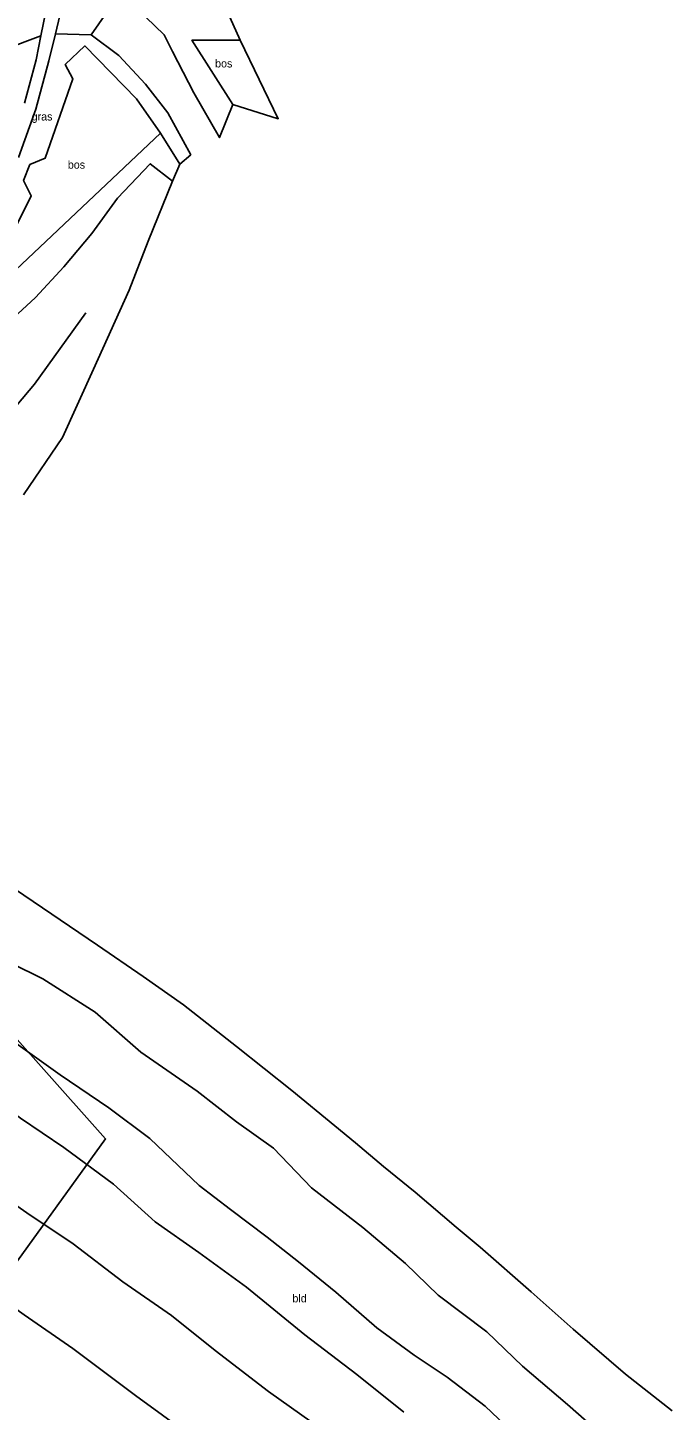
# Model space of a CAD drawing. Extents: x 154825 to 158680, y 370717 to 378075.
# Drawn here: x 157974.4 to 158055, y 372312.7 to 372485.5 of the extents above; entities that cross this region are included whole.
import ezdxf

# ---------------------------------------------------------------- set-up
doc = ezdxf.new("R2010")
doc.units = 0
for name, color, linetype in [('bos(vs)', 7, 'Continuous'), ('bouwland_akkerland(vs)', 7, 'Continuous'), ('cultuurscheiding', 7, 'Continuous'), ('grazige vegetatie(vs)', 7, 'Continuous'), ('hoogteverschillijn', 7, 'Continuous'), ('maaiveldlijn algemeen - gesloten verharding', 7, 'Continuous'), ('maaiveldlijn algemeen - onverhard', 7, 'Continuous'), ('maaiveldlijn algemeen - open verharding', 7, 'Continuous'), ('raster - hek', 7, 'Continuous'), ('vlak_akkerland', 7, 'Continuous'), ('vlak_Bos', 7, 'Continuous'), ('vlak_Grazige_vegetatie', 7, 'Continuous')]:
    doc.layers.add(name, color=color, linetype=linetype)

msp = doc.modelspace()

# ---------------------------------------------------------------- linework, layer by layer
at = {"layer": 'bos(vs)'}
for points in [[(158000.96, 372483.91), (157994.94, 372483.92), (158000.04, 372475.88)], [(157991.01, 372472.3), (157988.03, 372476.61), (157981.58, 372483.22), (157979.12, 372480.89), (157980.07, 372479.08), (157976.61, 372469.17), (157974.7, 372468.37), (157973.91, 372466.38), (157974.87, 372464.48), (157972.22, 372459.1), (157970.9, 372459.77), (157969.76, 372457.97), (157970.99, 372456.73), (157964.89, 372448.46), (157965.36, 372448.1)]]:
    msp.add_lwpolyline(points, dxfattribs=at)
at = {"layer": 'cultuurscheiding'}
msp.add_lwpolyline([(157970.2, 372327.32), (157984.17, 372346.6), (157927.5, 372410.28)], dxfattribs=at)
at = {"layer": 'hoogteverschillijn'}
for points in [[(157973.9, 372427.12), (157978.77, 372434.26), (157982.66, 372442.8), (157987.12, 372452.67), (157989.46, 372458.82), (157992.54, 372466.3), (157989.74, 372468.49), (157985.63, 372464.17), (157982.43, 372459.76), (157978.95, 372455.59), (157975.42, 372451.75), (157970.46, 372447.24)], [(157967.28, 372431.48), (157975.28, 372440.95), (157981.69, 372449.85)], [(157913.99, 372390.27), (157919.62, 372384.71), (157926.74, 372379.79), (157934.4, 372374.41), (157942.49, 372368.78), (157951.15, 372364.12), (157958.01, 372359.86), (157966.08, 372354.73), (157973.53, 372349.19), (157978.93, 372345.55), (157985.13, 372340.96), (157990.34, 372336.26), (157995.79, 372332.43), (158001.76, 372328.09), (158009.06, 372322.14), (158015.55, 372317.18), (158021.41, 372312.44)], [(158013.82, 372308.42), (158004.52, 372315.05), (157997.86, 372320.15), (157992.4, 372324.54), (157986.31, 372328.75), (157980.11, 372333.51), (157974.33, 372337.38), (157969.02, 372341.05), (157961.13, 372347.04), (157955.84, 372350.82), (157950.04, 372354.73), (157940.77, 372360.79), (157932.28, 372365.94), (157921.65, 372372.1), (157913.6, 372377.3), (157906.61, 372383.15), (157900.17, 372375.99), (157906.61, 372370.42), (157913.21, 372364.64)], [(158054.96, 372312.63), (158049.09, 372317.19), (158042.59, 372322.81), (158037.31, 372327.51), (158030.96, 372333.07), (158027.95, 372335.58), (158022.82, 372339.95), (158018.88, 372343.15), (158015.38, 372346.13), (158012.79, 372348.23), (158007.44, 372352.64), (158000.52, 372358.14), (157993.89, 372363.35), (157988.84, 372366.9), (157983.15, 372370.82), (157972.8, 372377.86)], [(157968.46, 372370.47), (157976.31, 372366.61), (157982.88, 372362.46), (157988.57, 372357.43), (157995.61, 372352.59), (158000.53, 372348.76), (158005.15, 372345.47), (158009.87, 372340.5), (158016.31, 372335.53), (158021.64, 372331.05), (158025.72, 372327.09), (158031.78, 372322.51), (158036.26, 372318.21), (158041.85, 372313.43), (158048.43, 372307.64)], [(157910.59, 372358.04), (157917.15, 372363.05), (157934.31, 372352.12), (157951.69, 372340.45), (157966.41, 372330.02), (157974, 372324.62), (157980.08, 372320.43), (157987.91, 372314.55), (157994.65, 372309.63)], [(158035.74, 372309.24), (158031.59, 372313.21), (158026.82, 372316.83), (158022.73, 372319.59), (158018.05, 372322.98), (158012.91, 372327.44), (158008.24, 372331.23), (158004.35, 372334.31), (157999.75, 372337.8), (157995.84, 372340.79), (157989.68, 372346.66), (157984.57, 372350.49), (157978.47, 372354.62), (157972.65, 372358.78)]]:
    msp.add_lwpolyline(points, dxfattribs=at)
at = {"layer": 'maaiveldlijn algemeen - gesloten verharding'}
for points in [[(157977.42, 372491.75), (157976.7, 372487.51), (157976.08, 372484.46)], [(157979.19, 372492.02), (157978.45, 372487.03), (157977.91, 372484.74)], [(157973.29, 372469.28), (157975.44, 372475.29), (157977.09, 372481.36), (157977.91, 372484.74)], [(157974.02, 372476.05), (157975.48, 372481.48), (157976.08, 372484.46)]]:
    msp.add_lwpolyline(points, dxfattribs=at)
at = {"layer": 'maaiveldlijn algemeen - onverhard'}
for points in [[(157998.41, 372471.76), (157995.2, 372477.35), (157992.51, 372482.51), (157991.46, 372484.61), (157988.08, 372487.9), (157985.23, 372488.72)], [(157982.36, 372484.59), (157985.81, 372482), (157989.13, 372478.43), (157991.93, 372474.83), (157994.79, 372469.6)]]:
    msp.add_lwpolyline(points, dxfattribs=at)
at = {"layer": 'maaiveldlijn algemeen - open verharding'}
for points in [[(157982.36, 372484.59), (157985.23, 372488.72)], [(157969.53, 372482.06), (157971.52, 372482.76), (157976.08, 372484.46)], [(157977.91, 372484.74), (157982.36, 372484.59)]]:
    msp.add_lwpolyline(points, dxfattribs=at)
at = {"layer": 'raster - hek'}
for points in [[(157997.63, 372491.37), (158000.96, 372483.91)], [(158000.96, 372483.91), (158005.73, 372474.11)], [(157991.01, 372472.3), (157965.36, 372448.1)], [(157993.44, 372468.45), (157991.01, 372472.3)]]:
    msp.add_lwpolyline(points, dxfattribs=at)
at = {"layer": 'vlak_akkerland'}
msp.add_lwpolyline([(157927.5, 372410.28), (157984.17, 372346.6), (157970.2, 372327.32), (157966.41, 372330.02), (157951.69, 372340.45), (157934.31, 372352.12), (157917.15, 372363.05), (157910.59, 372358.04), (157908.04, 372356.46), (157900.57, 372363.99), (157891.84, 372371.41), (157889.48, 372373.8), (157893.12, 372377.05), (157898.48, 372382.02), (157904.75, 372387.71), (157908.25, 372391.28), (157909.66, 372392.31), (157914, 372396.85), (157917.91, 372400.6), (157926.61, 372408.04), (157926.82, 372409.15), (157926.16, 372409.93), (157925.22, 372409.8), (157926.64, 372411.07)], close=True, dxfattribs=at)
at = {"layer": 'vlak_Bos'}
msp.add_lwpolyline([(158000.96, 372483.91), (158005.73, 372474.11), (158000.04, 372475.88), (157994.94, 372483.92)], close=True, dxfattribs=at)
for points in [[(157972.22, 372459.1), (157974.87, 372464.48), (157973.91, 372466.38), (157974.7, 372468.37), (157976.61, 372469.17), (157980.07, 372479.08), (157979.12, 372480.89), (157981.58, 372483.22), (157988.03, 372476.61), (157991.01, 372472.3), (157993.44, 372468.45), (157992.54, 372466.3), (157989.46, 372458.82), (157987.12, 372452.67), (157982.66, 372442.8), (157978.77, 372434.26), (157973.9, 372427.12)], [(157970.2, 372327.32), (157984.17, 372346.6), (157927.5, 372410.28)], [(157972.8, 372377.86), (157983.15, 372370.82), (157988.84, 372366.9), (157993.89, 372363.35), (158000.52, 372358.14), (158007.44, 372352.64), (158012.79, 372348.23), (158015.38, 372346.13), (158018.88, 372343.15), (158022.82, 372339.95), (158027.95, 372335.58), (158030.96, 372333.07), (158037.31, 372327.51), (158042.59, 372322.81), (158049.09, 372317.19), (158054.96, 372312.63)], [(157994.65, 372309.63), (157987.91, 372314.55), (157980.08, 372320.43), (157974, 372324.62)]]:
    msp.add_lwpolyline(points, dxfattribs=at)
at = {"layer": 'vlak_Grazige_vegetatie'}
for points in [[(157997.63, 372491.37), (158000.96, 372483.91), (157994.94, 372483.92), (158000.04, 372475.88), (157998.41, 372471.76), (157995.2, 372477.35), (157992.51, 372482.51), (157991.46, 372484.61), (157988.08, 372487.9)], [(157971.52, 372482.76), (157976.08, 372484.46), (157975.48, 372481.48), (157974.02, 372476.05)], [(157973.29, 372469.28), (157975.44, 372475.29), (157977.09, 372481.36), (157977.91, 372484.74), (157982.36, 372484.59), (157985.81, 372482), (157989.13, 372478.43), (157991.93, 372474.83), (157994.79, 372469.6), (157993.44, 372468.45), (157991.01, 372472.3), (157988.03, 372476.61), (157981.58, 372483.22), (157979.12, 372480.89), (157980.07, 372479.08), (157976.61, 372469.17), (157974.7, 372468.37), (157973.91, 372466.38), (157974.87, 372464.48), (157972.22, 372459.1)]]:
    msp.add_lwpolyline(points, dxfattribs=at)

# ---------------------------------------------------------------- texts
at = {"layer": 'bos(vs)'}
for p in [(157997.84, 372480.52), (157979.44, 372467.87)]:
    msp.add_text('bos', height=1, dxfattribs=at).set_placement(p)
at = {"layer": 'bouwland_akkerland(vs)'}
msp.add_text('bld', height=1, dxfattribs=at).set_placement((158007.5, 372326.18))
at = {"layer": 'grazige vegetatie(vs)'}
msp.add_text('gras', height=1, dxfattribs=at).set_placement((157974.92, 372473.89))

doc.saveas('drawing.dxf')
